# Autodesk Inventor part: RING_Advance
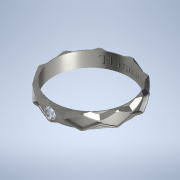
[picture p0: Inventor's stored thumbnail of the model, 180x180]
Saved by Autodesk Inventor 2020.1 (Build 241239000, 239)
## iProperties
Created: 2019-11
Part Number: RING_Advance
Material: Silver
Document SubType Name: Modeling
Designer: Synergysoft Dell02
Density: 10.49 g/cm^3
Appearance: Silver
Author: Synergysoft Dell02
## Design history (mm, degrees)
sketch "Sketch1"
  geometry: C1 r 10 at (0, 0); C2 r 11 at (0, 0); 1 further point
  constraints: 2 centre point, 2 coincident
  dimensions: "d0" = 20 diameter of C1; "d1" = 22 diameter of C2
extrude "Extrusion1" new body sketch "Sketch1" distance "d2" = 4; taper "d3" = 0 deg
chamfer "Chamfer1" distance "d4" = 0.2; stored, may be unused: second distance "d5" = 2, angle "d6" = 45 deg
workplane "Work Plane2"
sketch "Sketch5"
  geometry: L1 (-6.466, -8.899)-(6.466, 8.899) reference; L2 (0, 11)-(0, -11) reference; L3 (-10.462, 3.399)-(10.462, -3.399) reference; L4 (6.466, -8.899)-(-6.466, 8.899) reference; L5 (10.462, 3.399)-(-10.462, -3.399) reference; 1 further point
sketch "Sketch6"
  geometry: L1 (0, -11)-(0, 11) reference; L2 (6.466, 8.899)-(-6.466, -8.899) reference; L3 (10.462, -3.399)-(-10.462, 3.399) reference; L4 (-10.462, -3.399)-(10.462, 3.399) reference; L5 (-6.466, 8.899)-(6.466, -8.899) reference; 1 further point
workplane "Work Plane3"
workplane "Work Plane4"
workplane "Work Plane5"
workplane "Work Plane6"
workplane "Work Plane7"
workplane "Work Plane8"
workplane "Work Plane9"
workplane "Work Plane10"
workplane "Work Plane11"
workplane "Work Plane12"
workplane "Work Plane13"
workplane "Work Plane14"
workplane "Work Plane15"
workplane "Work Plane16"
workplane "Work Plane17"
workplane "Work Plane18"
workplane "Work Plane19"
workplane "Work Plane20"
workplane "Work Plane21"
workplane "Work Plane22"
feature "Sculpt1"
feature "Sculpt2"
workplane "Work Plane23"
sketch "Sketch8"
  geometry: L1 (-4, 2)-(4, 2); L2 (0.366, 3.8)-(-0.366, 3.8) reference; L3 (0.366, 3.8)-(-0.366, 3.8) reference; L4 (0, 3.8)-(0, 0); A1 r 30 centre (-13.41, 30.486) between (-4, 2) and (0, 3.65); A2 r 30 centre (-13.41, -26.486) between (0, 0.35) and (-4, 2); A3 r 30 centre (13.41, 30.486) between (0, 3.65) and (4, 2); A4 r 30 centre (13.41, -26.486) between (4, 2) and (0, 0.35); 3 further points
  constraints: 8 point on circle, 7 symmetric about line, 4 centre point, 4 end point, 2 midpoint, 2 point on line, 1 horizontal, 1 vertical, 3 other
  dimensions: "d27" = 30 radius of A1; "d43" = 0.15 distance from line of A1.end L2; "d46" = 8 distance of L1.start L1.end; "d47" = 3.3 diameter of A1.end L1
extrude "Extrusion3" cut sketch "Sketch8" distance "d44" = 10; taper "d45" = -5 deg
sketch "Sketch10"
  geometry: C1 r 10 at (0, 0); 1 further point
  constraints: 1 centre point
  dimensions: "d40" = 20 diameter of C1
extrude "Extrusion2" cut sketch "Sketch10" extent not by distance; stored distance "d37" = 10; taper "d38" = 0 deg
patch "Boundary Patch1" dims "d48" = 5, "d49" = 5, "d50" = 5, "d51" = 5, "d52" = 0
thicken "Thicken1" dims "d53" = 0.8, "d54" = 0.5
pattern_circular "Circular Pattern2" dims angle "d56" = 360 deg
pattern_circular "Circular Pattern3" dims angle "d63" = 36 deg
pattern_circular "Circular Pattern4" dims angle "d66" = 108 deg
pattern_circular "Circular Pattern5" dims angle "d69" = 180 deg
pattern_circular "Circular Pattern6" dims angle "d72" = 252 deg
pattern_circular "Circular Pattern7" dims angle "d75" = 324 deg
sketch "Sketch12"
  geometry: C1 r 9.9 at (0, 0); C2 r 10.1 at (0, 0); 1 further point
  constraints: 2 centre point, 2 coincident
  dimensions: "d58" = 19.8 diameter of C1; "d59" = 20.2 diameter of C2
extrude "Extrusion4" join sketch "Sketch12" distance "d60" = 4; taper "d61" = 0 deg
sketch "Sketch13"
  geometry: L1 (-9, 3.5)-(9, 3.5); L2 (9, 3.5)-(9, 0.5); L3 (9, 0.5)-(-9, 0.5); L4 (-9, 0.5)-(-9, 3.5); L5 (9.9, 4)-(9.9, 0) reference; 4 further points
  constraints: 3 midpoint, 1 horizontal, 1 horizontal alignment, 1 vertical alignment, 2 other
  dimensions: "d86" = 3 distance of L1.end L2.end; "d87" = 18 distance of L2.end L3.end
emboss "Emboss3" sketch "Sketch13" dims "d18" = 360 deg (derived), "d88" = 0.1, "d89" = 0
workplane "Work Plane26"
sketch "Sketch14"
  geometry: L1 (0, 1.5)-(1.061, 1.061); L2 (1.061, 1.061)-(1.5, 0); L3 (1.5, 0)-(1.061, -1.061); L4 (1.061, -1.061)-(0, -1.5); L5 (0, -1.5)-(-1.061, -1.061); L6 (-1.061, -1.061)-(-1.5, 0); L7 (-1.5, 0)-(-1.061, 1.061); L8 (-1.061, 1.061)-(0, 1.5); 2 further points
  constraints: 16 end point, 1 vertical alignment, 17 other
  dimensions: "d90" = 3 distance of L2.end L6.end; "d91" = 2 distance of point (0, -2) point (0, 0); "d92" = 3 distance of L4.end L1.start
workplane "Work Plane27"
workaxis "Work Axis1"
workpoint "Work Point2"
loft "Loft2" dims "d94" = 0, "d95" = 90 deg, "d96" = 0, "d97" = 90 deg
workplane "Work Plane28"
sketch "Sketch15"
  geometry: L1 (-1.5, 0)-(-1.061, 1.061) reference; L2 (-1.061, 1.061)-(0, 1.5) reference; L3 (0, 1.5)-(1.061, 1.061) reference; L4 (1.061, 1.061)-(1.5, 0) reference; L5 (1.5, 0)-(1.061, -1.061) reference; L6 (1.061, -1.061)-(0, -1.5) reference; L7 (0, -1.5)-(-1.061, -1.061) reference; L8 (-1.061, -1.061)-(-1.5, 0) reference; L9 (0, 1.229)-(-0.869, 0.869); L10 (-0.869, 0.869)-(-1.229, 0); L11 (-1.229, 0)-(-0.869, -0.869); L12 (-0.869, -0.869)-(0, -1.23); L13 (0, -1.23)-(0.869, -0.869); L14 (0.869, -0.869)-(1.229, 0); L15 (1.229, 0)-(0.869, 0.869); L16 (0.869, 0.869)-(0, 1.229); 1 further point
  constraints: 16 end point, 7 other
  dimensions: "d99" = 0.25 distance between parallel lines of L2 L9
workpoint "Work Point4"
sketch "3D Sketch1"
loft "Loft4" dims "d104" = 0, "d105" = 90 deg, "d106" = 0, "d107" = 90 deg, "d108" = 0, "d109" = 90 deg
loft "Loft5" dims "d112" = 0, "d113" = 90 deg, "d114" = 0, "d115" = 90 deg, "d116" = 0, "d117" = 90 deg
  node "Edges2"
workplane "Work Plane29"
workpoint "Work Point5"
loft "Loft6" dims "d119" = 0, "d120" = 90 deg, "d121" = 0, "d122" = 90 deg, "d123" = 0, "d124" = 90 deg
chamfer "Chamfer2" distance "d125" = 0.2; stored, may be unused: second distance "d126" = 2, angle "d127" = 45 deg
chamfer "Chamfer3" distance "d128" = 0.2; stored, may be unused: second distance "d129" = 2, angle "d130" = 45 deg
body "Solid1"
sketch "Sketch4"
  geometry: L1 (0, -11)-(0, 11); L2 (10.462, -3.399)-(-10.462, 3.399); L3 (6.466, 8.899)-(-6.466, -8.899); L4 (-6.466, 8.899)-(6.466, -8.899); L5 (-10.462, -3.399)-(10.462, 3.399); C1 r 11 at (0, 0) reference; A1 r 11 centre (0, 0) between (0, -11) and (0, 11); 5 further points
  constraints: 10 end point, 5 midpoint, 2 coincident, 2 point on circle, 1 centre point, 1 vertical, 19 other
  dimensions: "d18" = 360 deg dimension on point (0, 0) L1.start (derived)
body "Srf1"
body "Srf2"
body "Srf3"
body "Srf4"
body "Srf5"
body "Solid2"
node "Project Cut Edges1"
patch "Boundary Patch2"
patch "Boundary Patch3"
patch "Boundary Patch4"
patch "Boundary Patch5"
other parameters: "d93" = -0.5, "d98" = 0.5, "d118" = 0.2
